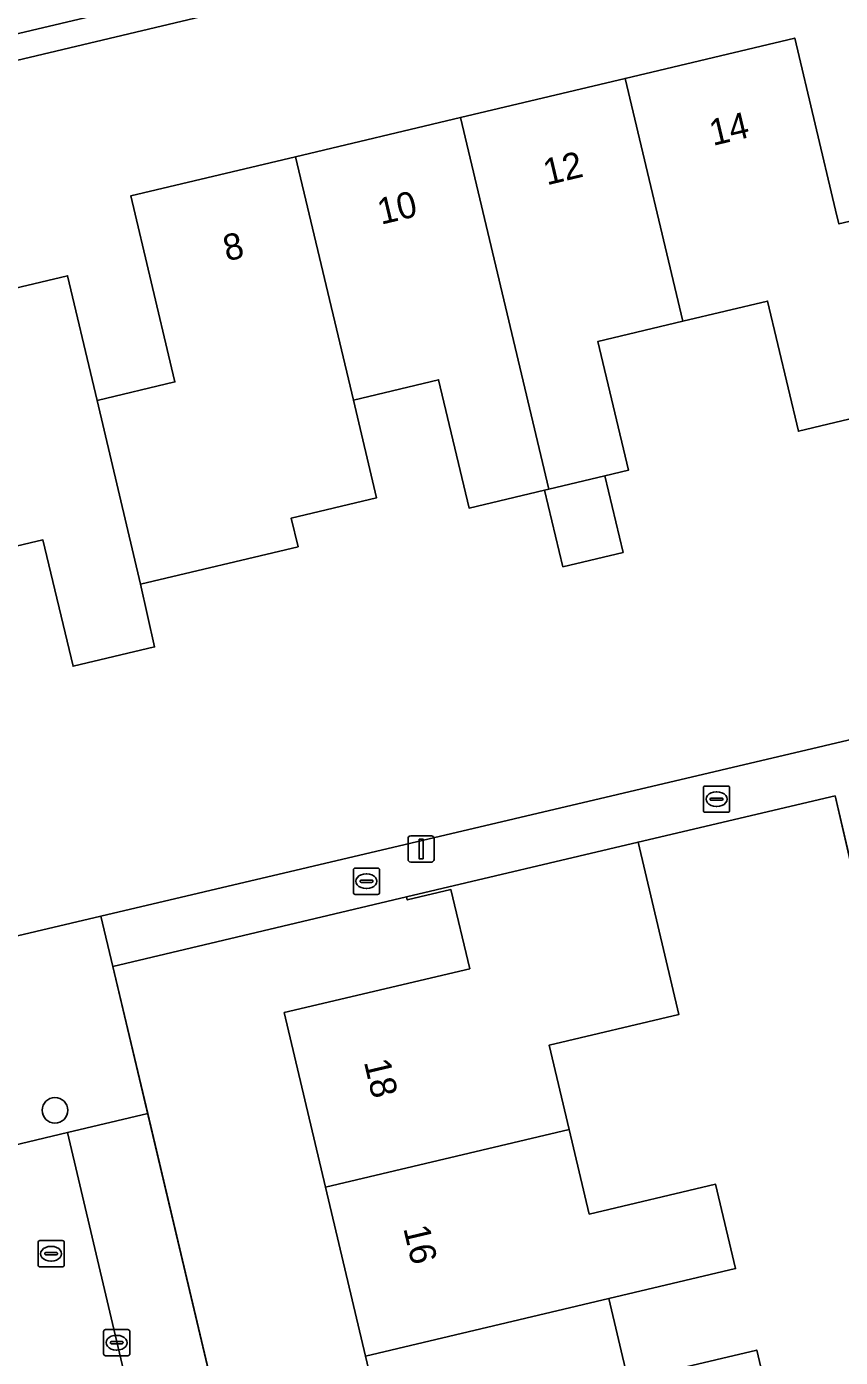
# Model space of a CAD drawing. Extents: x 157648 to 158502, y 379212 to 380938.
# Drawn here: x 158275.4 to 158306.5, y 380781.8 to 380832.6 of the extents above; entities that cross this region are included whole.
import ezdxf

# ---------------------------------------------------------------- set-up
doc = ezdxf.new("R2010")
doc.units = 0
for name, color, linetype in [('IMGEO_Boom', 7, 'Continuous'), ('IMGEO_Erf', 7, 'Continuous'), ('IMGEO_Hek', 7, 'Continuous'), ('IMGEO_Kolk', 7, 'Continuous'), ('IMGEO_Lichtmast', 7, 'Continuous'), ('IMGEO_Pand', 7, 'Continuous'), ('IMGEO_Pand_nummerreeks', 7, 'Continuous'), ('IMGEO_Rijbaan_lokaal_open', 7, 'Continuous'), ('IMGEO_Rioolput', 7, 'Continuous'), ('IMGEO_Voetpad_open', 7, 'Continuous')]:
    doc.layers.add(name, color=color, linetype=linetype)

msp = doc.modelspace()

# ---------------------------------------------------------------- linework, layer by layer
at = {"layer": 'IMGEO_Boom'}
msp.add_circle((158276.529, 380791.241), 0.489, dxfattribs=at)
at = {"layer": 'IMGEO_Erf'}
for points in [[(158312.07, 380840.074), (158256.672, 380826.915), (158255.725, 380826.659)], [(158253.038, 380822.214), (158253.257, 380821.342), (158255.128, 380821.779), (158255.611, 380819.715), (158256.852, 380814.564), (158258.797, 380815.029), (158257.957, 380818.539), (158264.358, 380820.06), (158270.624, 380821.549), (158277.009, 380823.066), (158278.013, 380818.841), (158278.138, 380818.315), (158281.104, 380819.02), (158280.977, 380819.556), (158279.419, 380826.113), (158285.707, 380827.607), (158291.999, 380829.102), (158298.275, 380830.594), (158304.745, 380832.131), (158306.303, 380825.574), (158306.43, 380825.041), (158309.351, 380825.735)], [(158311.02, 380818.596), (158304.887, 380817.139), (158303.708, 380822.1), (158300.475, 380821.332), (158297.239, 380820.563), (158298.406, 380815.653), (158297.501, 380815.438), (158298.195, 380812.518), (158295.9, 380811.972), (158295.206, 380814.892), (158292.325, 380814.208), (158291.163, 380819.1)], [(158291.163, 380819.1), (158287.91, 380818.327), (158288.795, 380814.6), (158285.54, 380813.827), (158285.8, 380812.735), (158279.785, 380811.305), (158280.326, 380808.912), (158277.218, 380808.173), (158276.072, 380812.996), (158272.84, 380812.228)], [(158269.909, 380796.676), (158278.284, 380798.647), (158313.745, 380806.99)]]:
    msp.add_lwpolyline(points, dxfattribs=at)
for points in [[(158306.826, 380800.924), (158306.285, 380803.232), (158298.77, 380801.471), (158300.325, 380794.9), (158295.381, 380793.729), (158296.144, 380790.505), (158296.908, 380787.281), (158301.728, 380788.422), (158302.49, 380785.204), (158297.65, 380784.058), (158298.39, 380780.934), (158303.297, 380782.096), (158304.701, 380776.167), (158309.611, 380777.228), (158310.36, 380774.064), (158305.528, 380772.92), (158306.281, 380769.738), (158307.034, 380766.557), (158311.907, 380767.711), (158313.394, 380761.443), (158320.838, 380763.175), (158317.035, 380779.21), (158312.187, 380778.039)], [(158305.431, 380763.021), (158298.376, 380761.349), (158296.915, 380767.519), (158295.366, 380774.062), (158297.09, 380774.47), (158297.615, 380774.594), (158296.899, 380777.616), (158296.331, 380777.482), (158289.781, 380775.931), (158288.376, 380781.865), (158286.851, 380788.305), (158285.273, 380794.966), (158292.347, 380796.642), (158291.633, 380799.659), (158289.967, 380799.265), (158289.939, 380799.382), (158278.739, 380796.726), (158280.066, 380791.118), (158288.473, 380755.581), (158304.545, 380759.344), (158304.48, 380759.617), (158306.144, 380760.011)]]:
    msp.add_lwpolyline(points, close=True, dxfattribs=at)
at = {"layer": 'IMGEO_Hek'}
for points in [[(158323.379, 380831.566), (158329, 380808.131), (158314.304, 380804.661), (158313.745, 380806.99), (158278.284, 380798.647)], [(158298.77, 380801.471), (158306.285, 380803.232), (158312.187, 380778.039), (158317.035, 380779.21), (158320.838, 380763.175), (158313.394, 380761.443)], [(158289.939, 380799.382), (158278.739, 380796.726)], [(158278.284, 380798.647), (158269.909, 380796.676)], [(158278.739, 380796.726), (158288.473, 380755.581)]]:
    msp.add_lwpolyline(points, dxfattribs=at)
at = {"layer": 'IMGEO_Kolk'}
for p, q in [((158301.26, 380802.681), (158301.26, 380803.533)), ((158301.335, 380803.607), (158302.187, 380803.607)), ((158301.748, 380803.387), (158301.773, 380803.387)), ((158302.261, 380803.533), (158302.261, 380802.681)), ((158301.519, 380803.101), (158301.519, 380803.113)), ((158301.957, 380803.064), (158301.559, 380803.064)), ((158301.562, 380803.15), (158301.96, 380803.15)), ((158301.771, 380802.827), (158301.746, 380802.827)), ((158302.003, 380803.113), (158302.003, 380803.101)), ((158302.187, 380802.607), (158301.335, 380802.607)), ((158287.909, 380799.551), (158287.909, 380800.403)), ((158287.984, 380800.477), (158288.836, 380800.477)), ((158288.397, 380800.257), (158288.422, 380800.257)), ((158288.91, 380800.403), (158288.91, 380799.551)), ((158288.168, 380799.971), (158288.168, 380799.983)), ((158288.606, 380799.934), (158288.208, 380799.934)), ((158288.211, 380800.02), (158288.609, 380800.02)), ((158288.652, 380799.983), (158288.652, 380799.971)), ((158288.836, 380799.477), (158287.984, 380799.477)), ((158288.42, 380799.697), (158288.395, 380799.697)), ((158278.383, 380781.953), (158278.383, 380782.805)), ((158278.458, 380782.879), (158279.31, 380782.879)), ((158278.871, 380782.659), (158278.896, 380782.659)), ((158279.384, 380782.805), (158279.384, 380781.953)), ((158278.642, 380782.373), (158278.642, 380782.385)), ((158279.08, 380782.336), (158278.682, 380782.336)), ((158278.685, 380782.422), (158279.083, 380782.422)), ((158278.894, 380782.099), (158278.869, 380782.099)), ((158279.126, 380782.385), (158279.126, 380782.373)), ((158279.31, 380781.879), (158278.458, 380781.879))]:
    msp.add_line(p, q, dxfattribs=at)
for points in [[(158301.26, 380802.681), (158301.26, 380803.533)], [(158301.335, 380803.607), (158302.187, 380803.607)], [(158302.261, 380803.533), (158302.261, 380802.681)], [(158302.187, 380802.607), (158301.335, 380802.607)], [(158287.909, 380799.551), (158287.909, 380800.403)], [(158287.984, 380800.477), (158288.836, 380800.477)], [(158288.91, 380800.403), (158288.91, 380799.551)], [(158288.836, 380799.477), (158287.984, 380799.477)], [(158278.383, 380781.953), (158278.383, 380782.805)], [(158278.458, 380782.879), (158279.31, 380782.879)], [(158279.384, 380782.805), (158279.384, 380781.953)], [(158279.31, 380781.879), (158278.458, 380781.879)]]:
    msp.add_lwpolyline(points, dxfattribs=at)
for centre, radius, start, end in [((158301.337, 380803.531), 0.0765, 91.552, 178.448), ((158301.337, 380803.531), 0.0765, 91.552, 178.448), ((158302.185, 380803.531), 0.0765, 1.552, 88.448), ((158302.185, 380803.531), 0.0765, 1.552, 88.448), ((158301.559, 380803.11), 0.0403, 85.8775, 175.7526), ((158301.556, 380803.1), 0.0366, 178.938, 274.7102), ((158301.96, 380803.107), 0.043, 264.8664, 352.4533), ((158301.964, 380803.112), 0.0386, 1.7309, 96.639), ((158301.337, 380802.683), 0.0765, 181.552, 268.448), ((158301.337, 380802.683), 0.0765, 181.552, 268.448), ((158302.185, 380802.683), 0.0765, 271.552, 358.448), ((158302.185, 380802.683), 0.0765, 271.552, 358.448), ((158287.986, 380800.401), 0.0765, 91.552, 178.448), ((158287.986, 380800.401), 0.0765, 91.552, 178.448), ((158288.834, 380800.401), 0.0765, 1.552, 88.448), ((158288.834, 380800.401), 0.0765, 1.552, 88.448), ((158288.208, 380799.98), 0.0403, 85.8775, 175.7526), ((158288.205, 380799.97), 0.0366, 178.938, 274.7102), ((158288.609, 380799.977), 0.043, 264.8664, 352.4533), ((158288.613, 380799.982), 0.0386, 1.7309, 96.639), ((158287.986, 380799.553), 0.0765, 181.552, 268.448), ((158287.986, 380799.553), 0.0765, 181.552, 268.448), ((158288.834, 380799.553), 0.0765, 271.552, 358.448), ((158288.834, 380799.553), 0.0765, 271.552, 358.448), ((158278.46, 380782.803), 0.0765, 91.552, 178.448), ((158278.46, 380782.803), 0.0765, 91.552, 178.448), ((158279.308, 380782.803), 0.0765, 1.552, 88.448), ((158279.308, 380782.803), 0.0765, 1.552, 88.448), ((158278.682, 380782.382), 0.0403, 85.8775, 175.7526), ((158278.679, 380782.372), 0.0366, 178.938, 274.7102), ((158279.083, 380782.379), 0.043, 264.8664, 352.4533), ((158279.087, 380782.384), 0.0386, 1.7309, 96.639), ((158278.46, 380781.955), 0.0765, 181.552, 268.448), ((158278.46, 380781.955), 0.0765, 181.552, 268.448), ((158279.308, 380781.955), 0.0765, 271.552, 358.448), ((158279.308, 380781.955), 0.0765, 271.552, 358.448)]:
    msp.add_arc(centre, radius, start, end, dxfattribs=at)
for centre, major_axis, ratio, start_param, end_param in [((158301.747, 380803.107), (-0.387, 0.002), 0.722429, 4.712389, 7.853982), ((158301.772, 380803.107), (-0.39, 0.002), 0.717154, 1.570796, 4.712389), ((158288.396, 380799.977), (-0.387, 0.002), 0.722429, 4.712389, 7.853982), ((158288.421, 380799.977), (-0.39, 0.002), 0.717154, 1.570796, 4.712389), ((158278.87, 380782.379), (-0.387, 0.002), 0.722429, 4.712389, 7.853982), ((158278.895, 380782.379), (-0.39, 0.002), 0.717154, 1.570796, 4.712389)]:
    msp.add_ellipse(centre, major_axis=major_axis, ratio=ratio, start_param=start_param, end_param=end_param, dxfattribs=at)
at = {"layer": 'IMGEO_Lichtmast'}
for p, q in [((158289.996, 380800.808), (158289.996, 380801.608)), ((158289.996, 380801.608), (158289.996, 380800.808)), ((158290.096, 380801.708), (158290.886, 380801.708)), ((158290.886, 380801.708), (158290.096, 380801.708)), ((158290.986, 380801.608), (158290.986, 380800.808)), ((158290.986, 380800.808), (158290.986, 380801.608)), ((158290.886, 380800.708), (158290.096, 380800.708)), ((158290.096, 380800.708), (158290.886, 380800.708))]:
    msp.add_line(p, q, dxfattribs=at)
msp.add_lwpolyline([(158290.416, 380801.583), (158290.566, 380801.583), (158290.566, 380800.833), (158290.416, 380800.833), (158290.416, 380801.583)], dxfattribs=at)
for centre, start, end in [((158290.096, 380801.608), 90, 180), ((158290.096, 380801.608), 90, 180), ((158290.886, 380801.608), 0, 90), ((158290.886, 380801.608), 360, 90), ((158290.096, 380800.808), 180, 270), ((158290.096, 380800.808), 180, 270), ((158290.886, 380800.808), 270, 0), ((158290.886, 380800.808), 270, 0)]:
    msp.add_arc(centre, 0.1, start, end, dxfattribs=at)
at = {"layer": 'IMGEO_Pand'}
for points in [[(158311.02, 380818.596), (158309.351, 380825.735), (158306.43, 380825.041), (158306.303, 380825.574), (158304.745, 380832.131), (158298.275, 380830.594), (158300.475, 380821.332), (158303.708, 380822.1), (158304.887, 380817.139)], [(158298.275, 380830.594), (158291.999, 380829.102), (158295.365, 380814.93), (158297.501, 380815.438), (158298.406, 380815.653), (158297.239, 380820.563), (158300.475, 380821.332)], [(158291.999, 380829.102), (158285.707, 380827.607), (158287.91, 380818.327), (158291.163, 380819.1), (158292.325, 380814.208), (158295.206, 380814.892), (158295.365, 380814.93)], [(158285.707, 380827.607), (158279.419, 380826.113), (158280.977, 380819.556), (158281.104, 380819.02), (158278.138, 380818.315), (158279.785, 380811.305), (158285.8, 380812.735), (158285.54, 380813.827), (158288.795, 380814.6), (158287.91, 380818.327)], [(158270.624, 380821.549), (158272.84, 380812.228), (158276.072, 380812.996), (158277.218, 380808.173), (158280.326, 380808.912), (158279.785, 380811.305), (158278.138, 380818.315), (158278.013, 380818.841), (158277.009, 380823.066)], [(158297.501, 380815.438), (158295.365, 380814.93), (158295.206, 380814.892), (158295.9, 380811.972), (158298.195, 380812.518)], [(158286.851, 380788.305), (158296.144, 380790.505), (158295.381, 380793.729), (158300.325, 380794.9), (158298.77, 380801.471), (158289.939, 380799.382), (158289.967, 380799.265), (158291.633, 380799.659), (158292.347, 380796.642), (158285.273, 380794.966)], [(158288.376, 380781.865), (158297.65, 380784.058), (158302.49, 380785.204), (158301.728, 380788.422), (158296.908, 380787.281), (158296.144, 380790.505), (158286.851, 380788.305)], [(158288.376, 380781.865), (158289.781, 380775.931), (158296.331, 380777.482), (158296.899, 380777.616), (158297.615, 380774.594), (158297.638, 380774.495), (158304.701, 380776.167), (158303.297, 380782.096), (158298.39, 380780.934), (158297.65, 380784.058)]]:
    msp.add_lwpolyline(points, close=True, dxfattribs=at)
at = {"layer": 'IMGEO_Rijbaan_lokaal_open'}
for points in [[(158255.725, 380826.659), (158256.672, 380826.915), (158256.423, 380827.895), (158322.34, 380843.453), (158317.438, 380864.207), (158335.841, 380868.585), (158335.368, 380870.628)], [(158273.504, 380776.015), (158280.032, 380777.559), (158277.001, 380790.391), (158274.929, 380789.894), (158271.262, 380789.038), (158263.643, 380787.23), (158263.394, 380788.266), (158259.536, 380787.359), (158255.678, 380786.452), (158255.935, 380785.414), (158223.948, 380777.852), (158220.271, 380776.983), (158195.501, 380771.154), (158191.823, 380770.281), (158179.865, 380767.493), (158181.411, 380760.862), (158191.095, 380763.183), (158194.781, 380764.047), (158206.903, 380766.947), (158210.582, 380767.794), (158224.132, 380771.019), (158227.228, 380771.756), (158233.729, 380773.304), (158248.445, 380776.778)]]:
    msp.add_lwpolyline(points, dxfattribs=at)
at = {"layer": 'IMGEO_Rioolput'}
for p, q in [((158275.882, 380785.346), (158275.882, 380786.198)), ((158275.957, 380786.272), (158276.809, 380786.272)), ((158276.37, 380786.052), (158276.395, 380786.052)), ((158276.883, 380786.198), (158276.883, 380785.346)), ((158276.141, 380785.766), (158276.141, 380785.778)), ((158276.579, 380785.729), (158276.181, 380785.729)), ((158276.184, 380785.815), (158276.582, 380785.815)), ((158276.625, 380785.778), (158276.625, 380785.766)), ((158276.809, 380785.272), (158275.957, 380785.272)), ((158276.393, 380785.492), (158276.368, 380785.492))]:
    msp.add_line(p, q, dxfattribs=at)
for points in [[(158275.882, 380785.346), (158275.882, 380786.198)], [(158275.957, 380786.272), (158276.809, 380786.272)], [(158276.883, 380786.198), (158276.883, 380785.346)], [(158276.809, 380785.272), (158275.957, 380785.272)]]:
    msp.add_lwpolyline(points, dxfattribs=at)
for centre, radius, start, end in [((158275.959, 380786.196), 0.0765, 91.552, 178.448), ((158275.959, 380786.196), 0.0765, 91.552, 178.448), ((158276.807, 380786.196), 0.0765, 1.552, 88.448), ((158276.807, 380786.196), 0.0765, 1.552, 88.448), ((158276.181, 380785.775), 0.0403, 85.8775, 175.7526), ((158276.178, 380785.765), 0.0366, 178.938, 274.7102), ((158276.582, 380785.772), 0.043, 264.8664, 352.4533), ((158276.586, 380785.777), 0.0386, 1.7309, 96.639), ((158275.959, 380785.348), 0.0765, 181.552, 268.448), ((158275.959, 380785.348), 0.0765, 181.552, 268.448), ((158276.807, 380785.348), 0.0765, 271.552, 358.448), ((158276.807, 380785.348), 0.0765, 271.552, 358.448)]:
    msp.add_arc(centre, radius, start, end, dxfattribs=at)
for centre, major_axis, ratio, start_param, end_param in [((158276.369, 380785.772), (-0.387, 0.002), 0.722429, 4.712389, 7.853982), ((158276.394, 380785.772), (-0.39, 0.002), 0.717154, 1.570796, 4.712389)]:
    msp.add_ellipse(centre, major_axis=major_axis, ratio=ratio, start_param=start_param, end_param=end_param, dxfattribs=at)
at = {"layer": 'IMGEO_Voetpad_open'}
for points in [[(158321.132, 380857.819), (158320.425, 380860.796), (158320.132, 380862.029), (158320.751, 380864.05), (158335.303, 380867.521), (158336.047, 380867.696), (158335.841, 380868.585), (158317.438, 380864.207), (158322.34, 380843.453), (158256.423, 380827.895), (158256.672, 380826.915), (158312.07, 380840.074), (158320.897, 380842.175), (158321.058, 380841.488), (158322.972, 380841.959), (158324.771, 380842.402), (158324.11, 380845.231), (158322.701, 380851.22)], [(158322.972, 380841.959), (158321.058, 380841.488), (158323.379, 380831.566), (158329, 380808.131), (158314.304, 380804.661), (158313.745, 380806.99), (158278.284, 380798.647), (158278.739, 380796.726), (158289.939, 380799.382), (158298.77, 380801.471), (158306.285, 380803.232), (158306.826, 380800.924), (158308.853, 380801.397), (158318.481, 380803.643), (158334.498, 380807.379), (158335.11, 380804.894), (158364.564, 380811.841), (158363.902, 380814.78), (158339.383, 380808.977), (158338.72, 380811.781), (158337.257, 380811.425), (158330.575, 380809.862)], [(158278.739, 380796.726), (158278.284, 380798.647), (158269.909, 380796.676), (158270.361, 380794.772), (158264.211, 380793.312), (158262.059, 380792.802), (158262.099, 380792.614), (158260.269, 380792.168), (158260.834, 380789.811), (158258.195, 380789.188), (158259.536, 380787.359), (158263.394, 380788.266), (158263.643, 380787.23), (158271.262, 380789.038), (158274.929, 380789.894), (158277.001, 380790.391), (158280.066, 380791.118)]]:
    msp.add_lwpolyline(points, close=True, dxfattribs=at)
msp.add_lwpolyline([(158294.972, 380728.159), (158294.286, 380731.078), (158291.182, 380744.148), (158289.647, 380750.631), (158288.94, 380753.648), (158288.473, 380755.581), (158280.066, 380791.118), (158277.001, 380790.391), (158280.032, 380777.559), (158280.79, 380774.351), (158281.657, 380770.677), (158284.513, 380758.542), (158285.387, 380754.879), (158285.857, 380752.928), (158286.732, 380749.252), (158290.986, 380731.308), (158291.886, 380727.513), (158292.832, 380723.522), (158293.7, 380719.842), (158299.024, 380697.594), (158299.078, 380697.367), (158302.589, 380699.148)], dxfattribs=at)

# ---------------------------------------------------------------- texts
at = {"layer": 'IMGEO_Pand_nummerreeks'}
for s, rotation, p in [('14', 13.3668, (158301.623, 380828.017)), ('12', 13.3671, (158295.288, 380826.513)), ('10', 13.3671, (158288.963, 380825.009)), ('8', 13.3671, (158283.079, 380823.611)), ('18', 283.3237, (158288.307, 380793.088)), ('16', 283.3237, (158289.81, 380786.745))]:
    msp.add_text(s, height=1, rotation=rotation, dxfattribs=at).set_placement(p)

doc.saveas('drawing.dxf')
